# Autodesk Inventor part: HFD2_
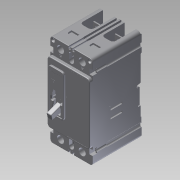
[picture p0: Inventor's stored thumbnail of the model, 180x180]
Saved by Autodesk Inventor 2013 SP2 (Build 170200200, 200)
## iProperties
Created: 2014-08
Part Number: HFD2_
Material: Generic
Document SubType Name: Modeling
Designer: DM/JS
Density: 1 g/cm^3
Description: TYPE HFD THERMAL MAGNETIC CIRCUIT BREAKERS TWO POLE, SERIES C
Translation Standard: STEP AP214IS
FileName: Y:\ECO-062745\WIP\New\FD2_.stp
PreProcessor: Autodesk Inventor 2012
PostProcessor: Build: 219, Release: 2012 SP2 - Date: Fri 04/27/2012
Sent Units: inch
Uncertainty: 0.00039370078740199997
MXEDIT: false
MXINVTNRV: INV Versioned Component|HFD2_|003.0
Author: DM/JS
Revision Number: 003
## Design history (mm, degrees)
node "HFD2_"
node "L1"
node "L2"
node "T1"
node "T2"
body "Solid1"
node "Base1"
